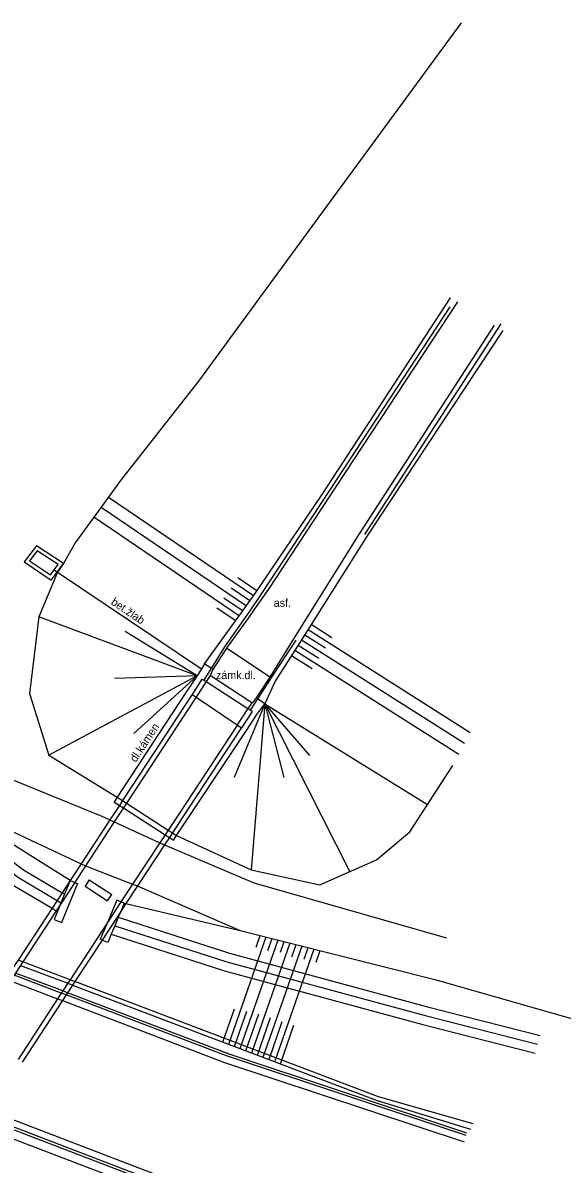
# Model space of a CAD drawing. Extents: x -541281 to -539153, y -1183881 to -1182141.
# Drawn here: x -539258.6 to -539214.8, y -1182483.7 to -1182391 of the extents above; entities that cross this region are included whole.
import ezdxf

# ---------------------------------------------------------------- set-up
doc = ezdxf.new("R2010")
doc.units = 0
for name, color, linetype in [('Vrstva 10', 7, 'Continuous'), ('Vrstva 11', 7, 'Continuous'), ('Vrstva 14', 7, 'Continuous'), ('Vrstva 15', 7, 'Continuous'), ('Vrstva 40', 7, 'Continuous'), ('Vrstva 7', 7, 'Continuous'), ('Vrstva 9', 7, 'Continuous')]:
    doc.layers.add(name, color=color, linetype=linetype)

msp = doc.modelspace()

# ---------------------------------------------------------------- linework, layer by layer
at = {"layer": 'Vrstva 10'}
for p, q in [((-539233.829, -1182429.669), (-539223.318, -1182413.671)), ((-539220.354, -1182415.555), (-539231.312, -1182432.497)), ((-539231.312, -1182432.497), (-539236.646, -1182441.023)), ((-539257.533, -1182433.475), (-539258.538, -1182434.768)), ((-539255.326, -1182434.916), (-539257.533, -1182433.475)), ((-539257.466, -1182433.877), (-539258.104, -1182434.698)), ((-539255.758, -1182434.992), (-539257.466, -1182433.877)), ((-539258.538, -1182434.768), (-539256.331, -1182436.252)), ((-539258.104, -1182434.698), (-539256.4, -1182435.844)), ((-539255.841, -1182435.601), (-539255.326, -1182434.916)), ((-539256.331, -1182436.252), (-539255.841, -1182435.601)), ((-539239.997, -1182438.869), (-539242.094, -1182441.796)), ((-539242.094, -1182441.796), (-539243.208, -1182443.508)), ((-539238.589, -1182444.129), (-539242.094, -1182441.796)), ((-539236.646, -1182441.023), (-539238.589, -1182444.129)), ((-539244.126, -1182443.453), (-539244.486, -1182444.039)), ((-539243.882, -1182443.056), (-539244.126, -1182443.453)), ((-539243.208, -1182443.508), (-539243.882, -1182443.056)), ((-539243.208, -1182443.508), (-539243.423, -1182443.996)), ((-539244.486, -1182444.039), (-539245.351, -1182445.304)), ((-539244.086, -1182444.29), (-539243.74, -1182444.498)), ((-539243.423, -1182443.996), (-539243.74, -1182444.498)), ((-539243.74, -1182444.498), (-539240.357, -1182446.699)), ((-539240.042, -1182446.225), (-539243.423, -1182443.996)), ((-539238.589, -1182444.129), (-539239.691, -1182445.81)), ((-539245.351, -1182445.304), (-539250.981, -1182453.878)), ((-539244.888, -1182445.544), (-539244.562, -1182445.765)), ((-539244.966, -1182445.665), (-539249.756, -1182452.962)), ((-539244.637, -1182445.881), (-539249.427, -1182453.178)), ((-539240.042, -1182446.225), (-539240.357, -1182446.699)), ((-539240.042, -1182446.225), (-539239.917, -1182446.137)), ((-539239.691, -1182445.81), (-539239.917, -1182446.137)), ((-539238.995, -1182446.294), (-539239.691, -1182445.81)), ((-539239.621, -1182447.17), (-539238.995, -1182446.294)), ((-539240.357, -1182446.699), (-539241.226, -1182448.024)), ((-539240.011, -1182446.926), (-539240.884, -1182448.257)), ((-539240.471, -1182448.467), (-539239.621, -1182447.17)), ((-539240.011, -1182446.926), (-539240.357, -1182446.699)), ((-539241.264, -1182448.082), (-539246.031, -1182455.345)), ((-539240.918, -1182448.309), (-539245.685, -1182455.572)), ((-539241.226, -1182448.024), (-539241.264, -1182448.082)), ((-539240.884, -1182448.257), (-539240.918, -1182448.309)), ((-539246.162, -1182457.009), (-539240.471, -1182448.467)), ((-539249.756, -1182452.962), (-539250.542, -1182454.163)), ((-539250.981, -1182453.878), (-539251.213, -1182454.283)), ((-539249.427, -1182453.178), (-539250.212, -1182454.377)), ((-539250.542, -1182454.163), (-539250.796, -1182454.551)), ((-539250.212, -1182454.377), (-539250.465, -1182454.764)), ((-539246.031, -1182455.345), (-539246.838, -1182456.569)), ((-539245.685, -1182455.572), (-539246.49, -1182456.795)), ((-539246.838, -1182456.569), (-539247.082, -1182456.94)), ((-539246.733, -1182457.164), (-539246.406, -1182457.374)), ((-539246.406, -1182457.374), (-539246.162, -1182457.009)), ((-539253.236, -1182460.612), (-539253.57, -1182461.125)), ((-539253.57, -1182461.125), (-539251.753, -1182462.307)), ((-539253.236, -1182460.612), (-539251.419, -1182461.794)), ((-539251.753, -1182462.307), (-539251.419, -1182461.794)), ((-539259.63, -1182468.795), (-539255.807, -1182470.254)), ((-539255.807, -1182470.254), (-539255.411, -1182470.405)), ((-539255.411, -1182470.405), (-539242.268, -1182475.422)), ((-539242.268, -1182475.422), (-539222.798, -1182481.886)), ((-539226.842, -1182492.543), (-539261.274, -1182479.395))]:
    msp.add_line(p, q, dxfattribs=at)
for points in [[(-539239.997, -1182438.869), (-539238.654, -1182436.995), (-539233.829, -1182429.669)], [(-539256.4, -1182435.844), (-539256.091, -1182435.433), (-539255.758, -1182434.992)], [(-539244.086, -1182444.29), (-539244.888, -1182445.544), (-539244.966, -1182445.665)], [(-539243.74, -1182444.498), (-539244.562, -1182445.765), (-539244.637, -1182445.881)], [(-539244.562, -1182445.765), (-539241.226, -1182448.024), (-539240.884, -1182448.257)], [(-539250.981, -1182453.878), (-539250.542, -1182454.163), (-539250.212, -1182454.377), (-539246.838, -1182456.569), (-539246.49, -1182456.795), (-539246.162, -1182457.009)], [(-539250.796, -1182454.551), (-539251.566, -1182455.729), (-539253.894, -1182459.287), (-539254.464, -1182460.158)], [(-539250.465, -1182454.764), (-539251.205, -1182455.895), (-539253.534, -1182459.455), (-539254.135, -1182460.373)], [(-539251.213, -1182454.283), (-539250.796, -1182454.551), (-539250.465, -1182454.764), (-539247.082, -1182456.94), (-539246.733, -1182457.164)], [(-539247.082, -1182456.94), (-539247.511, -1182457.592), (-539249.72, -1182460.945), (-539250.672, -1182462.391), (-539250.806, -1182462.595)], [(-539246.49, -1182456.795), (-539246.733, -1182457.164), (-539247.129, -1182457.765), (-539249.325, -1182461.099), (-539250.27, -1182462.535), (-539250.459, -1182462.821)], [(-539254.464, -1182460.158), (-539254.787, -1182460.649), (-539255.436, -1182461.648), (-539255.847, -1182462.277), (-539256.257, -1182462.906), (-539259.001, -1182467.111), (-539259.19, -1182467.401), (-539259.599, -1182468.028), (-539259.711, -1182468.199), (-539260.006, -1182468.652), (-539262.655, -1182472.712)], [(-539254.135, -1182460.373), (-539254.416, -1182460.803), (-539255.607, -1182462.627), (-539255.919, -1182463.106), (-539258.625, -1182467.254), (-539258.814, -1182467.544), (-539259.223, -1182468.171), (-539259.335, -1182468.342), (-539259.63, -1182468.795), (-539262.326, -1182472.927)], [(-539250.806, -1182462.595), (-539251.77, -1182464.071), (-539254.797, -1182468.708), (-539254.985, -1182468.995), (-539255.397, -1182469.626), (-539255.509, -1182469.797), (-539255.807, -1182470.254), (-539259.025, -1182475.182)], [(-539250.459, -1182462.821), (-539250.684, -1182463.166), (-539252.201, -1182465.489), (-539254.401, -1182468.859), (-539254.589, -1182469.146), (-539255.001, -1182469.777), (-539255.113, -1182469.948), (-539255.411, -1182470.405), (-539258.678, -1182475.408)]]:
    msp.add_lwpolyline(points, dxfattribs=at)
at = {"layer": 'Vrstva 11'}
for p, q in [((-539261.59, -1182455.706), (-539253.894, -1182459.287)), ((-539251.566, -1182455.729), (-539251.205, -1182455.895)), ((-539251.205, -1182455.895), (-539247.511, -1182457.592)), ((-539247.129, -1182457.765), (-539239.884, -1182460.842)), ((-539253.894, -1182459.287), (-539253.534, -1182459.455)), ((-539253.534, -1182459.455), (-539249.72, -1182460.945)), ((-539254.787, -1182460.649), (-539254.416, -1182460.803)), ((-539249.72, -1182460.945), (-539249.325, -1182461.099)), ((-539239.884, -1182460.842), (-539224.221, -1182465.305)), ((-539255.436, -1182461.648), (-539255.247, -1182461.76)), ((-539256.257, -1182462.906), (-539255.919, -1182463.106)), ((-539255.919, -1182463.106), (-539255.827, -1182463.16)), ((-539250.405, -1182462.503), (-539250.684, -1182463.166)), ((-539250.405, -1182462.503), (-539250.672, -1182462.391)), ((-539256.101, -1182463.821), (-539255.5, -1182464.07)), ((-539251.77, -1182464.071), (-539252.341, -1182465.431)), ((-539250.881, -1182463.634), (-539241.844, -1182466.546)), ((-539251.464, -1182465.023), (-539242.27, -1182467.984)), ((-539240.977, -1182464.709), (-539225.173, -1182468.683)), ((-539252.201, -1182465.489), (-539252.341, -1182465.431)), ((-539251.742, -1182465.683), (-539252.201, -1182465.489)), ((-539241.844, -1182466.546), (-539225.775, -1182470.9)), ((-539255.509, -1182469.797), (-539259.335, -1182468.342)), ((-539255.397, -1182469.626), (-539259.223, -1182468.171)), ((-539242.27, -1182467.984), (-539226.157, -1182472.35)), ((-539225.173, -1182468.683), (-539209.369, -1182473.209)), ((-539255.001, -1182469.777), (-539255.397, -1182469.626)), ((-539255.113, -1182469.948), (-539255.509, -1182469.797)), ((-539242.092, -1182474.902), (-539255.113, -1182469.948)), ((-539225.775, -1182470.9), (-539216.634, -1182473.228)), ((-539226.157, -1182472.35), (-539217.038, -1182474.672)), ((-539222.632, -1182481.368), (-539242.092, -1182474.902)), ((-539227.034, -1182493.036), (-539261.571, -1182479.851))]:
    msp.add_line(p, q, dxfattribs=at)
for points in [[(-539270.655, -1182452.921), (-539265.858, -1182455.042), (-539261.946, -1182457.267), (-539258.572, -1182459.791), (-539255.436, -1182461.648)], [(-539260.189, -1182452.183), (-539252.208, -1182455.434), (-539251.566, -1182455.729)], [(-539271.155, -1182454.34), (-539266.534, -1182456.384), (-539262.77, -1182458.525), (-539259.406, -1182461.041), (-539259.292, -1182461.109), (-539256.257, -1182462.906)], [(-539247.511, -1182457.592), (-539247.165, -1182457.75), (-539247.129, -1182457.765)], [(-539254.787, -1182460.649), (-539255.247, -1182461.76), (-539255.537, -1182462.46), (-539255.607, -1182462.627)], [(-539254.416, -1182460.803), (-539254.186, -1182460.898), (-539255.5, -1182464.07)], [(-539249.325, -1182461.099), (-539249.164, -1182461.162), (-539240.977, -1182464.709)], [(-539250.672, -1182462.391), (-539251.004, -1182462.251), (-539251.77, -1182464.071)], [(-539255.607, -1182462.627), (-539255.827, -1182463.16), (-539256.101, -1182463.821)], [(-539250.684, -1182463.166), (-539250.881, -1182463.634), (-539251.173, -1182464.329), (-539251.464, -1182465.023), (-539251.742, -1182465.683)]]:
    msp.add_lwpolyline(points, dxfattribs=at)
at = {"layer": 'Vrstva 14'}
for p, q in [((-539223.03, -1182391.002), (-539233.997, -1182405.949)), ((-539233.997, -1182405.949), (-539244.356, -1182420.101)), ((-539234.331, -1182429.316), (-539223.907, -1182413.326)), ((-539219.669, -1182415.998), (-539230.662, -1182432.673)), ((-539252.483, -1182430.63), (-539254.386, -1182433.243)), ((-539230.662, -1182432.673), (-539236.145, -1182441.321)), ((-539255.816, -1182435.618), (-539257.336, -1182439.23)), ((-539243.882, -1182443.056), (-539240.592, -1182438.472)), ((-539257.336, -1182439.23), (-539258.079, -1182445.456)), ((-539236.145, -1182441.321), (-539238.134, -1182444.457)), ((-539238.134, -1182444.457), (-539238.995, -1182446.294)), ((-539258.079, -1182445.456), (-539256.523, -1182450.475)), ((-539256.523, -1182450.475), (-539250.981, -1182453.878)), ((-539227.198, -1182456.705), (-539223.729, -1182451.304)), ((-539254.787, -1182460.649), (-539262.058, -1182456.082)), ((-539229.927, -1182458.989), (-539227.198, -1182456.705)), ((-539246.162, -1182457.009), (-539240.08, -1182459.794)), ((-539234.52, -1182461.015), (-539229.927, -1182458.989)), ((-539240.08, -1182459.794), (-539234.52, -1182461.015)), ((-539255.847, -1182462.277), (-539255.537, -1182462.46)), ((-539250.405, -1182462.503), (-539250.27, -1182462.535)), ((-539250.27, -1182462.535), (-539240.977, -1182464.709)), ((-539251.173, -1182464.329), (-539242.057, -1182467.265)), ((-539258.814, -1182467.544), (-539254.985, -1182468.995)), ((-539242.057, -1182467.265), (-539225.966, -1182471.625)), ((-539254.985, -1182468.995), (-539254.589, -1182469.146)), ((-539254.589, -1182469.146), (-539229.862, -1182478.521)), ((-539225.966, -1182471.625), (-539216.836, -1182473.95)), ((-539229.862, -1182478.521), (-539222.272, -1182480.836)), ((-539262.07, -1182480.617), (-539227.308, -1182493.872))]:
    msp.add_line(p, q, dxfattribs=at)
for points in [[(-539244.356, -1182420.101), (-539250.697, -1182428.179), (-539252.483, -1182430.63)], [(-539240.592, -1182438.472), (-539239.721, -1182437.258), (-539234.331, -1182429.316)], [(-539254.386, -1182433.243), (-539255.326, -1182434.916), (-539255.816, -1182435.618)], [(-539256.091, -1182435.433), (-539255.841, -1182435.601), (-539255.816, -1182435.618), (-539244.126, -1182443.453)], [(-539270.866, -1182453.648), (-539266.196, -1182455.713), (-539262.358, -1182457.896), (-539258.989, -1182460.416), (-539255.847, -1182462.277)]]:
    msp.add_lwpolyline(points, dxfattribs=at)
at = {"layer": 'Vrstva 15'}
for p, q in [((-539239.91, -1182437.536), (-539251.69, -1182429.542)), ((-539240.471, -1182438.363), (-539252.278, -1182430.35)), ((-539241.033, -1182439.191), (-539252.868, -1182431.159)), ((-539239.629, -1182437.122), (-539241.174, -1182436.074)), ((-539240.191, -1182437.949), (-539241.72, -1182436.912)), ((-539240.752, -1182438.777), (-539242.303, -1182437.724)), ((-539241.314, -1182439.604), (-539242.886, -1182438.537)), ((-539244.486, -1182444.039), (-539257.336, -1182439.23)), ((-539235.209, -1182439.845), (-539233.533, -1182440.908)), ((-539244.486, -1182444.039), (-539250.325, -1182440.435)), ((-539235.744, -1182440.69), (-539234.069, -1182441.752)), ((-539235.477, -1182440.267), (-539222.298, -1182448.623)), ((-539236.28, -1182441.534), (-539234.604, -1182442.597)), ((-539236.012, -1182441.112), (-539222.77, -1182449.508)), ((-539236.815, -1182442.379), (-539235.14, -1182443.441)), ((-539236.548, -1182441.956), (-539223.242, -1182450.393)), ((-539244.486, -1182444.039), (-539256.523, -1182450.475)), ((-539244.486, -1182444.039), (-539251.201, -1182444.242)), ((-539244.486, -1182444.039), (-539249.624, -1182448.705)), ((-539238.995, -1182446.294), (-539241.477, -1182452.293)), ((-539238.995, -1182446.294), (-539240.08, -1182459.794)), ((-539238.995, -1182446.294), (-539225.764, -1182454.473)), ((-539238.995, -1182446.294), (-539237.447, -1182452.293)), ((-539238.995, -1182446.294), (-539235.344, -1182450.499)), ((-539238.995, -1182446.294), (-539232.088, -1182459.942)), ((-539241.917, -1182473.95), (-539238.877, -1182465.237)), ((-539240.981, -1182474.305), (-539237.903, -1182465.482)), ((-539240.046, -1182474.66), (-539236.929, -1182465.727)), ((-539239.696, -1182466.069), (-539239.363, -1182465.115)), ((-539239.111, -1182475.014), (-539235.956, -1182465.972)), ((-539238.735, -1182466.35), (-539238.39, -1182465.36)), ((-539237.717, -1182466.467), (-539237.416, -1182465.604)), ((-539236.79, -1182466.844), (-539236.443, -1182465.849)), ((-539238.176, -1182475.369), (-539234.982, -1182466.216)), ((-539235.801, -1182467.046), (-539235.469, -1182466.094)), ((-539234.822, -1182467.275), (-539234.495, -1182466.339)), ((-539242.384, -1182473.773), (-539241.445, -1182471.083)), ((-539241.449, -1182474.128), (-539240.447, -1182471.257)), ((-539240.514, -1182474.482), (-539239.469, -1182471.489)), ((-539239.579, -1182474.837), (-539238.51, -1182471.775)), ((-539238.643, -1182475.192), (-539237.566, -1182472.104)), ((-539237.708, -1182475.546), (-539236.615, -1182472.414))]:
    msp.add_line(p, q, dxfattribs=at)
at = {"layer": 'Vrstva 7'}
for p, q in [((-539258.625, -1182467.254), (-539259.001, -1182467.111)), ((-539254.797, -1182468.708), (-539258.625, -1182467.254)), ((-539254.401, -1182468.859), (-539254.797, -1182468.708)), ((-539229.762, -1182478.223), (-539254.401, -1182468.859)), ((-539222.063, -1182480.427), (-539229.762, -1182478.223))]:
    msp.add_line(p, q, dxfattribs=at)
at = {"layer": 'Vrstva 9'}
for p, q in [((-539234.305, -1182429.88), (-539223.922, -1182414.073)), ((-539219.83, -1182415.46), (-539230.9, -1182432.546)), ((-539242.236, -1182441.68), (-539240.186, -1182438.743)), ((-539243.913, -1182444.394), (-539242.236, -1182441.68)), ((-539236.473, -1182441.125), (-539238.385, -1182444.068)), ((-539238.385, -1182444.068), (-539240.184, -1182446.812)), ((-539242.021, -1182474.715), (-539255.001, -1182469.777)), ((-539222.569, -1182481.178), (-539242.029, -1182474.712)), ((-539261.682, -1182480.022), (-539227.105, -1182493.223))]:
    msp.add_line(p, q, dxfattribs=at)
msp.add_lwpolyline([(-539240.186, -1182438.743), (-539239.327, -1182437.511), (-539234.305, -1182429.88)], dxfattribs=at)

# ---------------------------------------------------------------- texts
at = {"layer": 'Vrstva 40'}
for s, rotation, p in [('bet.žlab', 326.16455, (-539251.536, -1182438.186)), ('dl.kámen', 56.70964, (-539249.458, -1182451.103))]:
    msp.add_text(s, height=0.65, rotation=rotation, dxfattribs=at).set_placement(p)
for s, p in [('asf.', (-539238.261, -1182438.432)), ('zámk.dl.', (-539242.951, -1182444.298))]:
    msp.add_text(s, height=0.65, dxfattribs=at).set_placement(p)

doc.saveas('drawing.dxf')
